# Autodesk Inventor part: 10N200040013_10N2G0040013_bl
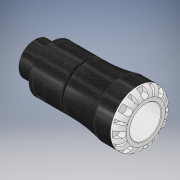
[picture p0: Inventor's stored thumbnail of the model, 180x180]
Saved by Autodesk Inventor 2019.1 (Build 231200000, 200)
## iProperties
Created: 2016-12
Part Number: 10N200040013_10N2G0040013_bl
Material: PVC-Piping
Description: PLASSON MALE ADAPTOR 40X1.1/4" SERIES 1
Document SubType Name: Modeling
Designer: KIM
Mass: 61.7504 g
Surface Area: 140.097 cm^2
Volume: 44.1074 cm^3
Density: 1.4 g/cm^3
Appearance: Black Cast
Author: KIM
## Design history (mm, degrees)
derived "10N20.ipt"
feature "Solid1::10N20.ipt" dims "ScaleForDerivedMember" = 10
tag "TaggingFeature1"
body "Solid1"
other parameters: "d0" = 142 [user parameter], "d1" = 30.66 [user parameter], "d6" = 73 [user parameter], "d8" = 59.5 [user parameter], "d13" = 8 [user parameter], "d14" = 8 [user parameter], "d15" = 0 [user parameter], "d17" = 360 deg [user parameter], "d19" = 8 deg [user parameter], "d20" = 0.8 [user parameter], "d21" = 0.8 [user parameter], "d22" = 8 deg [user parameter], "d24" = 0 [user parameter], "d26" = 360 deg [user parameter], "d32" = 0.925 [user parameter], "d33" = 7 [user parameter], "d34" = 41.91 [user parameter], "d35" = 5 [user parameter], "d38" = 22 [user parameter], "d39" = 1.2573 [user parameter], "d42" = 14 [user parameter], "d43" = 9.2 [user parameter], "d45" = 15.68 [user parameter], "d46" = 0 [user parameter], "d59" = 360 deg [user parameter], "d61" = 11.9 [user parameter], "d62" = 0.8 [user parameter], "d64" = 0 [user parameter], "d65" = 0.7 [user parameter], "d69" = 2 [user parameter], "d70" = 2.13 [user parameter], "d71" = 3 [user parameter], "d73" = 1 [user parameter], "H_" = 142 [user parameter], "l_" = 73 [user parameter], "R_" = 41.91 [user parameter], "l_2" = 22 [user parameter]
